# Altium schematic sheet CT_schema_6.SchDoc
size 300 x 247 mm
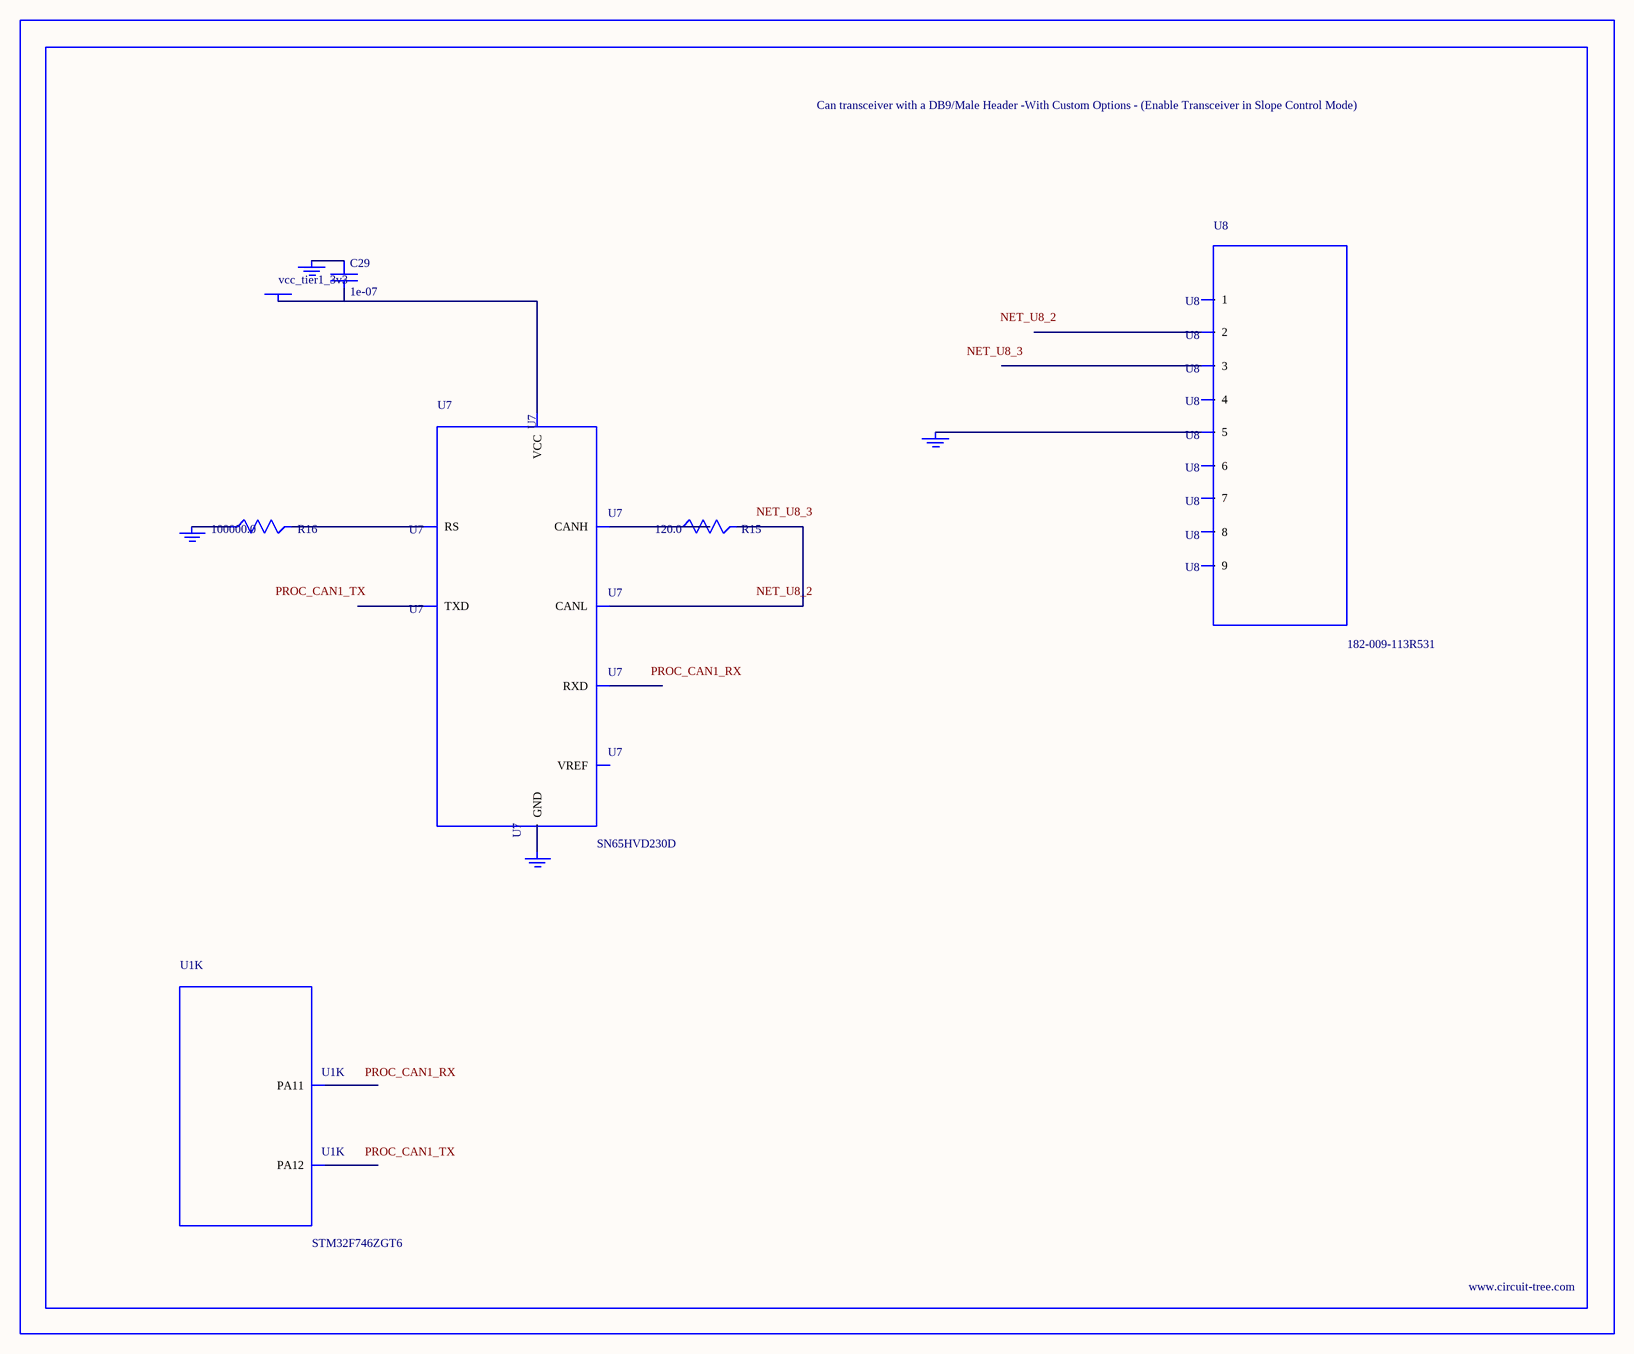
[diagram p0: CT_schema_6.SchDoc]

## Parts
BORDER5  (no value)
C29  1e-07  [C0402]
GND_INSTANCE_5_0  (no value)
GND_INSTANCE_5_1  (no value)
GND_INSTANCE_5_2  (no value)
GND_INSTANCE_5_3  (no value)
POWER_INSTANCE_5_0  vcc_tier1_3v3
R15  120.0  [R0603]
R16  100000.0  [R0603]
U1  STM32F746ZGT6  [LQFP144]  (part K of 12)
U7  SN65HVD230D  [SOIC-8]
U8  182-009-113R531  [182-009-MALE]

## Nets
NetC29_1: C29.1 GND_INSTANCE_5_0.0(GND)
NetC29_2: C29.2 POWER_INSTANCE_5_0.0(PWR) U7.3(VCC)
NetGND_INSTANCE_5_1_0: GND_INSTANCE_5_1.0(GND) R16.1
NetGND_INSTANCE_5_2_0: GND_INSTANCE_5_2.0(GND) U7.2(GND)
NetGND_INSTANCE_5_3_0: GND_INSTANCE_5_3.0(GND) U8.5
NetR15_1: R15.1 U7.7(CANH)
NetR15_2: R15.2 U7.6(CANL)
NetR16_2: R16.2 U7.8(RS)

Not connected (* = marked no-connect by the designer): U1 103(PA11) 104(PA12); U7 1(TXD) 4(RXD) 5(VREF); U8 1 2 3 4 6 7 8 9

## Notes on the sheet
- Labels drawn without touching a wire or pin: NET_U8_2, NET_U8_3, PROC_CAN1_RX, PROC_CAN1_TX

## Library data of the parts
BORDER5 = BORDER_PAGE5
C29 = C0402C104K3RACTU
GND_INSTANCE_5_0-GND_INSTANCE_5_3 = GND
POWER_INSTANCE_5_0 = PWR
R15 = RC0603JR-07120RL
R16 = RC0603JR-07100KL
